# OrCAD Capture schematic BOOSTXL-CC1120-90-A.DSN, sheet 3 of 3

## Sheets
3 CC112x: size B
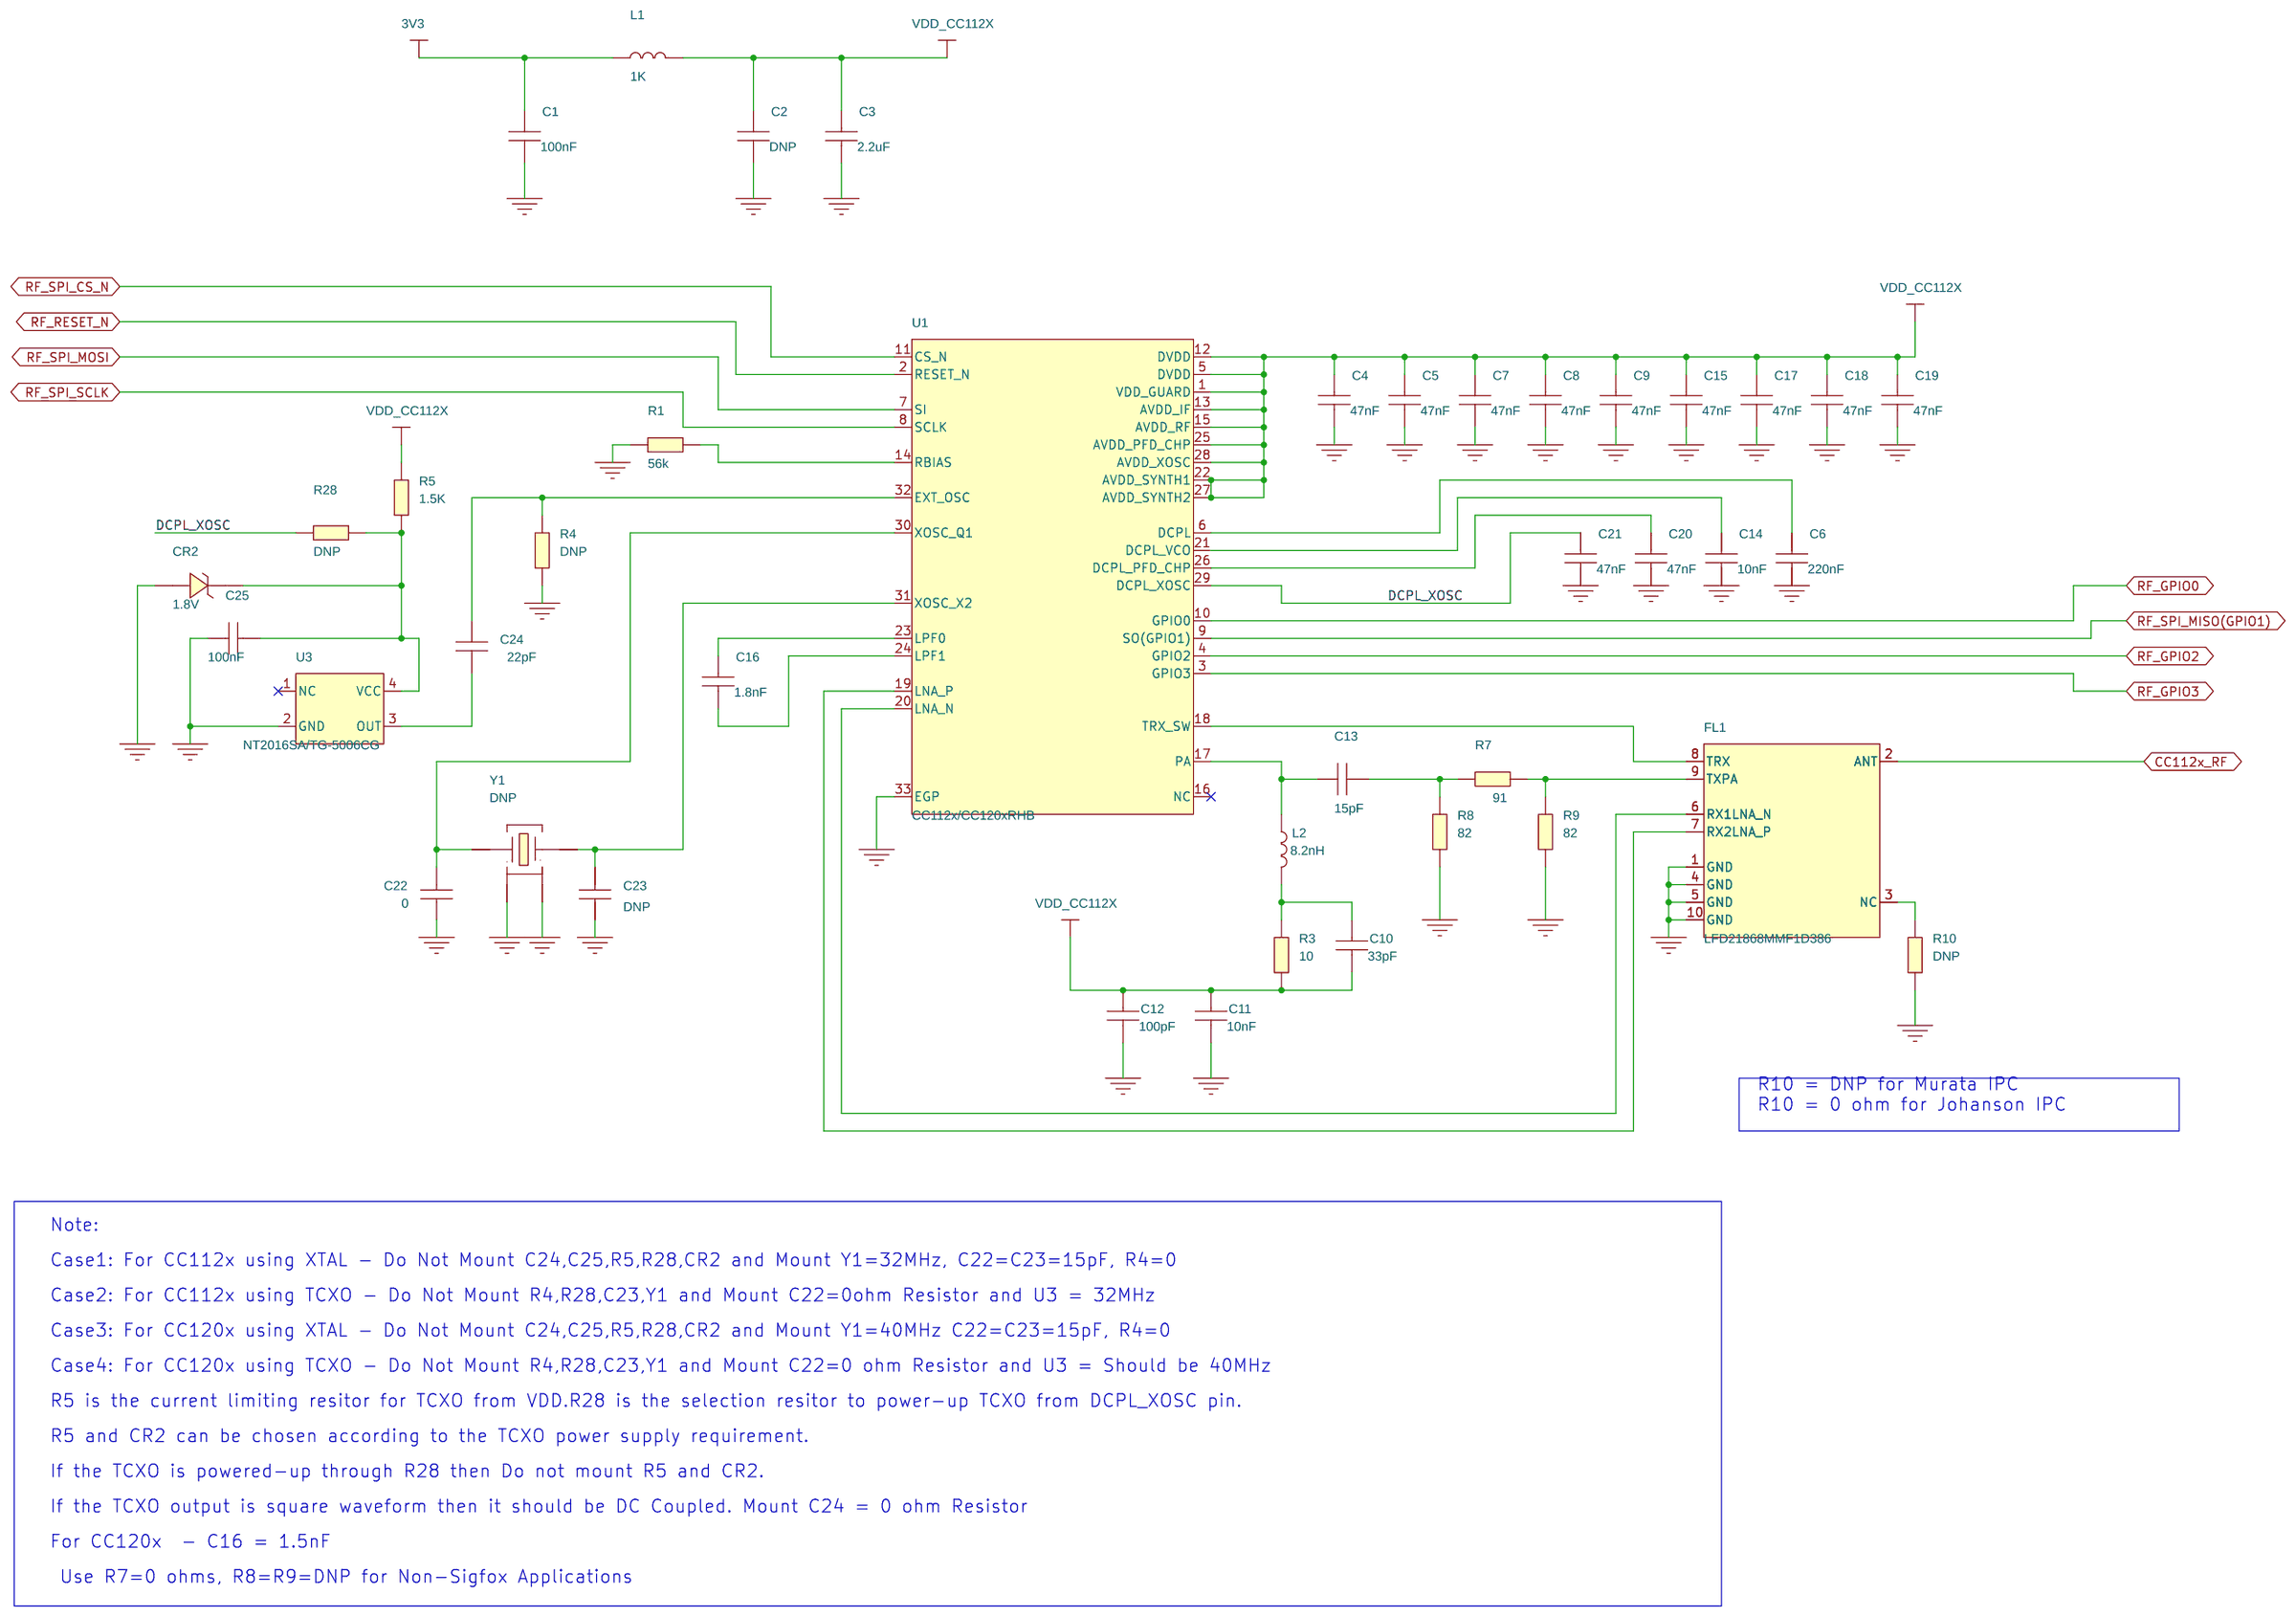
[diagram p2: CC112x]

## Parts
C1  100nF  [CAPC1005X60N]
C2  DNP  [CAPC1005X60N]
C3  2.2uF  [CAPC1608X90N]
C4  47nF  [CAPC1005X60N]
C5  47nF  [CAPC1005X60N]
C6  220nF  [CAPC1005X60N]
C7  47nF  [CAPC1005X60N]
C8  47nF  [CAPC1005X60N]
C9  47nF  [CAPC1005X60N]
C10  33pF  [CAPC1005X60N]
C11  10nF  [CAPC1005X60N]
C12  100pF  [CAPC1005X60N]
C13  15pF  [CAPC1005X60N]
C14  10nF  [CAPC1005X60N]
C15  47nF  [CAPC1005X60N]
C16  1.8nF  [CAPC1005X60N]
C17  47nF  [CAPC1005X60N]
C18  47nF  [CAPC1005X60N]
C19  47nF  [CAPC1005X60N]
C20  47nF  [CAPC1005X60N]
C21  47nF  [CAPC1005X60N]
C22  0  [CAPC1005X60N]
C23  DNP  [CAPC1005X60N]
C24  22pF  [CAPC1005X60N]
C25  100nF  [CAPC1005X60N]
CR2  1.8V  [SOD3716X135AN]
FL1  LFD21868MMF1D386  [FIL_LFD21868MMF1D386N]
L1  1K  [INDC1005X60N]
L2  8.2nH  [IND_LQW15AN]
R1  56k  [RESC1005X40N]
R3  10  [RESC1005X40N]
R4  DNP  [RESC1005X40N]
R5  1.5K  [RESC1005X40N]
R7  91  [RESC1005X40N]
R8  82  [RESC1005X40N]
R9  82  [RESC1005X40N]
R10  DNP  [RESC1005X40N]
R28  DNP  [RESC1005X40N]
U1  CC112x/CC120xRHB  [QFNFC50P500X500X100-33BN]
U3  NT2016SA/TG-5006CG  [OSCCC200X250X90-4BN]
Y1  DNP  [XTAL_FA128N]

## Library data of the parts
C1 C25 = CAPACITOR: CAPACITOR, CERAMIC X7R, 100nF, 10V, -10%/+10%, -55DEGC/+125DEGC, 0402, SMD; ALT_SYMBOLS: CAPC1005X60L,CAPC1005X60M; AutoDoc File: http://notefied-dynamic-precision.com/DB/Apps/Desktop/Item/Object.aspx?id=49911; Budget Currency: EUR; Budget Price: 0.006; Datasheet URL 1: http://search.murata.co.jp/Ceramy/image/img/w_hinm/L0005E.pdf; Datasheet URL 2: http://psearch.murata.com/capacitor/product/GRM155R71A104KA01%23.pdf; Definied Quality: INDUSTRIAL; Dielectric Type: X7R; Esd Level: N/A; FPLIST: CAPC1005X60N,CAPC1005X60L,CAPC1005X60M; Last Time Buy: N/A; Lead Time: 14; LifeCycle Status: GROWTH; MPN: GRM155R71A104KA01D; MPN Status: NRND; MSL: 1; MTBF: N/A; MTBF Standard: N/A; Manufacturer: MURATA; Max Oper Temp: +125DEGC; Max Tol: +10%; Min Oper Temp: -55DEGC; Min Tol: -10%; Mounting Type: SMD; NOTE Status: PREFERRED; Old Footprint: CAPC1005X60N,0402; PCB Package: 0402; Packing Size: 10000; Packing Type: TAPE_&_REEL; Part Number: 02-00760; Part Type: CAPACITOR\CERAMIC\0402; Revision: R008; RoHS Status: ROHS_COMPLIANT; Rtd Voltage: 10V; WEIGHT: 0.0016g
C2 = CAPACITOR: CAPACITOR, CERAMIC X7R, 100nF, 10V, -10%/+10%, -55DEGC/+125DEGC, 0402, SMD; ALT_SYMBOLS: CAPC1005X60L,CAPC1005X60M; AutoDoc File: http://notefied-dynamic-precision.com/DB/Apps/Desktop/Item/Object.aspx?id=49911; Budget Currency: EUR; Budget Price: 0.006; Capacitance: 100nF; Datasheet URL 1: http://search.murata.co.jp/Ceramy/image/img/w_hinm/L0005E.pdf; Datasheet URL 2: http://psearch.murata.com/capacitor/product/GRM155R71A104KA01%23.pdf; Definied Quality: INDUSTRIAL; Dielectric Type: X7R; Esd Level: N/A; FPLIST: CAPC1005X60N,CAPC1005X60L,CAPC1005X60M; Last Time Buy: N/A; Lead Time: 14; LifeCycle Status: GROWTH; MPN: GRM155R71A104KA01D; MPN Status: NRND; MSL: 1; MTBF: N/A; MTBF Standard: N/A; Manufacturer: MURATA; Max Oper Temp: +125DEGC; Max Tol: +10%; Min Oper Temp: -55DEGC; Min Tol: -10%; Mounting Type: SMD; NOTE Status: PREFERRED; Old Footprint: CAPC1005X60N,0402; PCB Package: 0402; Packing Size: 10000; Packing Type: TAPE_&_REEL; Part Number: 02-00760; Part Type: CAPACITOR\CERAMIC\0402; Revision: R008; RoHS Status: ROHS_COMPLIANT; Rtd Voltage: 10V; WEIGHT: 0.0016g
C3 = CAPACITOR: CAPACITOR, CERAMIC X5R, 2.2uF, 10V, -20%/+20%, -55DEGC/+85DEGC, 0603, SMD; ALT_SYMBOLS: CAPC1608X90L,CAPC1608X90M; AutoDoc File: http://notefied-dynamic-precision.com/DB/Apps/Desktop/Item/Object.aspx?id=50283; Budget Currency: EUR; Budget Price: 0.03; Datasheet URL 1: http://search.murata.co.jp/Ceramy/image/img/w_hinm/L0005E.pdf; Datasheet URL 2: http://psearch.murata.com/capacitor/product/GRM188R61A225ME34%23.pdf; Definied Quality: INDUSTRIAL; Dielectric Type: X5R; Esd Level: N/A; FPLIST: CAPC1608X90N,CAPC1608X90L,CAPC1608X90M; Last Time Buy: N/A; Lead Time: 10; LifeCycle Status: GROWTH; MPN: GRM188R61A225ME34D; MPN Status: NRND; MSL: 1; MTBF: N/A; MTBF Standard: N/A; Manufacturer: MURATA; Max Oper Temp: +85DEGC; Max Tol: +20%; Min Oper Temp: -55DEGC; Min Tol: -20%; Mounting Type: SMD; NOTE Status: PREFERRED; Old Footprint: CAPC1608X90N,0603; PCB Package: 0603; Packing Size: 4000; Packing Type: TAPE_&_REEL; Part Number: 02-01132; Part Type: CAPACITOR\CERAMIC\0603; Revision: R002; RoHS Status: ROHS_COMPLIANT; Rtd Voltage: 10V; WEIGHT: 0.0063g
C4 C5 C7-C9 C15 C17-C21 = CAPACITOR: CAPACITOR, CERAMIC, 47nF, 10%, X7R, 10V, 0402, SMD; ALT_SYMBOLS: CAPC1005X60L,CAPC1005X60M; AutoDoc File: http://notefied-dynamic-precision.com/DB/Apps/Desktop/Item/Object.aspx?id=49765; Budget Currency: EUR; Budget Price: 0.006; Datasheet URL 1: http://search.murata.co.jp/Ceramy/image/img/w_hinm/L0005E.pdf; Datasheet URL 2: http://psearch.murata.com/capacitor/product/GRM155R71A473KA01%23.pdf; Definied Quality: INDUSTRIAL; Dielectric Type: X7R; Esd Level: N/A; FPLIST: CAPC1005X60N,CAPC1005X60L,CAPC1005X60M; Last Time Buy: N/A; Lead Time: 10; LifeCycle Status: GROWTH; MPN: GRM155R71A473KA01D; MPN Status: NRND; MSL: 1; MTBF: N/A; MTBF Standard: N/A; Manufacturer: MURATA; Max Oper Temp: +125DEGC; Min Oper Temp: -55DEGC; Min Tol: -10%; Mounting Type: SMD; NOTE Status: PREFERRED; Old Footprint: CAPC1005X60N,0402; PCB Package: 0402; Packing Size: 10000; Packing Type: TAPE_&_REEL; Part Number: 02-00614; Part Type: CAPACITOR\CERAMIC\0402; Revision: R001; RoHS Status: ROHS_COMPLIANT; Rtd Voltage: 10V; WEIGHT: 0.0016g
C6 = CAPACITOR: CAPACITOR, CERAMIC X5R, 220nF, 10V, -10%/+10%, -55DEGC/+85DEGC, 0402, SMD; ALT_SYMBOLS: CAPC1005X60L,CAPC1005X60M; AutoDoc File: http://notefied-dynamic-precision.com/DB/Apps/Desktop/Item/Object.aspx?id=86035; Budget Currency: EUR; Budget Price: 0.014; Datasheet URL 1: http://search.murata.co.jp/Ceramy/image/img/w_hinm/L0005E.pdf; Datasheet URL 2: http://psearch.murata.com/capacitor/product/GRM155R61A224KE19%23.pdf; Definied Quality: INDUSTRIAL; Dielectric Type: X5R; Esd Level: N/A; FPLIST: CAPC1005X60N,CAPC1005X60L,CAPC1005X60M; Last Time Buy: N/A; Lead Time: 18; MPN: GRM155R61A224KE19D; MPN Status: ACTIVE; MSL: 1; MTBF: N/A; MTBF Standard: N/A; Manufacturer: MURATA; Max Oper Temp: +85DEGC; Max Tol: +10%; Min Oper Temp: -55DEGC; Min Tol: -10%; Mounting Type: SMD; NOTE Status: PREFERRED; PCB Package: 0402; Packing Size: 10000; Packing Type: TAPE_&_REEL; Part Number: 02-04353; Part Type: CAPACITOR\CERAMIC\0402; Revision: R001; RoHS Status: ROHS_COMPLIANT; Rtd Voltage: 10V; WEIGHT: 0.0016g
C10 = CAPACITOR: CAPACITOR, CERAMIC C0G/NP0, 33pF, 50V, -5%/+5%, -55DEGC/+125DEGC, 0402, SMD; ALT_SYMBOLS: CAPC1005X60M,CAPC1005X60L; AutoDoc File: http://notefied-dynamic-precision.com/DB/Apps/Desktop/Item/Object.aspx?id=86036; Budget Currency: EUR; Budget Price: 0.006; Datasheet URL 1: http://search.murata.co.jp/Ceramy/image/img/w_hinm/L0005E.pdf; Datasheet URL 2: http://psearch.murata.com/capacitor/product/GRM1555C1H330JA01%23.pdf; Definied Quality: INDUSTRIAL; Dielectric Type: C0G/NP0; Esd Level: N/A; FPLIST: CAPC1005X60N,CAPC1005X60M,CAPC1005X60L; Last Time Buy: N/A; Lead Time: 12; MPN: GRM1555C1H330JA01D; MPN Status: ACTIVE; MSL: 1; MTBF: N/A; MTBF Standard: N/A; Manufacturer: MURATA; Max Oper Temp: +125DEGC; Max TC: +30PPM/DEGC; Max Tol: +5%; Min Oper Temp: -55DEGC; Min TC: -30PPM/DEGC; Min Tol: -5%; Mounting Type: SMD; NOTE Status: PREFERRED; PCB Package: 0402; Packing Size: 10000; Packing Type: TAPE_&_REEL; Part Number: 02-04354; Part Type: CAPACITOR\CERAMIC\0402; Revision: R003; RoHS Status: ROHS_COMPLIANT; Rtd Voltage: 50V; WEIGHT: 0.0016g
C11 C14 = CAPACITOR: CAPACITOR, CERAMIC X7R, 10nF, 25V, -10%/+10%, -55DEGC/+125DEGC, 0402, SMD; ALT_SYMBOLS: CAPC1005X60L,CAPC1005X60M; AutoDoc File: http://notefied-dynamic-precision.com/DB/Apps/Desktop/Item/Object.aspx?id=73597; Budget Currency: EUR; Budget Price: 0.003; Cage Code: C0151; Datasheet URL 1: http://search.murata.co.jp/Ceramy/image/img/w_hinm/L0005E.pdf; Datasheet URL 2: http://psearch.murata.com/capacitor/product/GRM155R71E103KA01%23.pdf; Definied Quality: INDUSTRIAL; Dielectric Type: X7R; Esd Level: N/A; FPLIST: CAPC1005X60N,CAPC1005X60L,CAPC1005X60M; Last Time Buy: N/A; Lead Time: 10; MPN: GRM155R71E103KA01D; MPN Status: ACTIVE; MSL: N/A; MTBF: N/A; MTBF Standard: N/A; Manufacturer: MURATA; Max Oper Temp: +125DEGC; Max Tol: +10%; Min Oper Temp: -55DEGC; Min Tol: -10%; Mounting Type: SMD; NOTE Status: PREFERRED; PCB Package: 0402; Packing Size: 10000; Packing Type: TAPE_&_REEL; Part Number: 02-02314; Part Type: CAPACITOR\CERAMIC\0402; Revision: R002; RoHS Status: ROHS_COMPLIANT; Rtd Voltage: 25V; WEIGHT: 0.0016g
C12 = CAPACITOR: CAPACITOR, CERAMIC C0G/NP0, 100pF, 50V, -5%/+5%, -55DEGC/+125DEGC, 0402, SMD; ALT_SYMBOLS: CAPC1005X60L,CAPC1005X60M; AutoDoc File: http://notefied-dynamic-precision.com/DB/Apps/Desktop/Item/Object.aspx?id=86072; Budget Currency: EUR; Budget Price: 0.006; Datasheet URL 1: http://search.murata.co.jp/Ceramy/image/img/w_hinm/L0005E.pdf; Datasheet URL 2: http://psearch.murata.com/capacitor/product/GRM1555C1H101JA01%23.pdf; Definied Quality: INDUSTRIAL; Dielectric Type: C0G/NP0; Esd Level: N/A; FPLIST: CAPC1005X60N,CAPC1005X60L,CAPC1005X60M; Last Time Buy: N/A; Lead Time: 12; MPN: GRM1555C1H101JA01D; MPN Status: ACTIVE; MSL: 1; MTBF: N/A; MTBF Standard: N/A; Manufacturer: MURATA; Max Oper Temp: +125DEGC; Max TC: +30PPM/DEGC; Max Tol: +5%; Min Oper Temp: -55DEGC; Min TC: -30PPM/DEGC; Min Tol: -5%; Mounting Type: SMD; NOTE Status: PREFERRED; PCB Package: 0402; Packing Size: 10000; Packing Type: TAPE_&_REEL; Part Number: 02-04365; Part Type: CAPACITOR\CERAMIC\0402; Revision: R002; RoHS Status: ROHS_COMPLIANT; Rtd Voltage: 50V; WEIGHT: 0.0016g
C13 = CAPACITOR: CAPACITOR, CERAMIC C0G/NP0, 15pF, 50V, -5%/+5%, -55DEGC/+125DEGC, 0402, SMD; ALT_SYMBOLS: CAPC1005X60L,CAPC1005X60M; AutoDoc File: http://notefied-dynamic-precision.com/DB/Apps/Desktop/Item/Object.aspx?id=87791; Budget Currency: EUR; Budget Price: 0.005; Datasheet URL 1: http://search.murata.co.jp/Ceramy/image/img/w_hinm/L0005E.pdf; Datasheet URL 2: http://psearch.murata.com/capacitor/product/GRM1555C1H150JA01%23.pdf; Definied Quality: INDUSTRIAL; Dielectric Type: C0G/NP0; Esd Level: N/A; FPLIST: CAPC1005X60N,CAPC1005X60L,CAPC1005X60M; Last Time Buy: N/A; Lead Time: 12; MPN: GRM1555C1H150JA01D; MPN Status: ACTIVE; MSL: 1; MTBF: N/A; MTBF Standard: N/A; Manufacturer: MURATA; Max Oper Temp: +125DEGC; Max TC: +30PPM/DEGC; Max Tol: +5%; Min Oper Temp: -55DEGC; Min TC: -30PPM/DEGC; Min Tol: -5%; Mounting Type: SMD; NOTE Status: PREFERRED; PCB Package: 0402; Packing Size: 10000; Packing Type: TAPE_&_REEL; Part Number: 02-04673; Part Type: CAPACITOR\CERAMIC\0402; Revision: R001; RoHS Status: ROHS_COMPLIANT; Rtd Voltage: 50V; WEIGHT: 0.0016g
C16 = CAPACITOR: CAPACITOR, CERAMIC U2J, 1.8nF, 10V, -5%/+5%, -55DEGC/+125DEGC, 0402, SMD; ALT_SYMBOLS: CAPC1005X60L,CAPC1005X60M; AutoDoc File: http://notefied-dynamic-precision.com/DB/Apps/Desktop/Item/Object.aspx?id=86079; Budget Currency: EUR; Budget Price: 0.028; Datasheet URL 1: http://search.murata.co.jp/Ceramy/image/img/w_hinm/L0005E.pdf; Datasheet URL 2: http://psearch.murata.com/capacitor/product/GRM1557U1A182JA01%23.pdf; Definied Quality: INDUSTRIAL; Dielectric Type: U2J; Esd Level: N/A; FPLIST: CAPC1005X60N,CAPC1005X60L,CAPC1005X60M; Last Time Buy: N/A; Lead Time: 12; MPN: GRM1557U1A182JA01D; MPN Status: ACTIVE; MSL: 1; MTBF: N/A; MTBF Standard: N/A; Manufacturer: MURATA; Max Oper Temp: +125DEGC; Max TC: +120PPM/DEGC; Max Tol: +5%; Min Oper Temp: -55DEGC; Min TC: -750PPM/DEGC; Min Tol: -5%; Mounting Type: SMD; NOTE Status: PREFERRED; PCB Package: 0402; Packing Size: 10000; Packing Type: TAPE_&_REEL; Part Number: 02-04371; Part Type: CAPACITOR\CERAMIC\0402; Revision: R001; RoHS Status: ROHS_COMPLIANT; Rtd Voltage: 10V; WEIGHT: 0.0016g
C22 C23 = CAPACITOR: CAPACITOR, CERAMIC C0G/NP0, 15pF, 50V, -5%/+5%, -55DEGC/+125DEGC, 0402, SMD; ALT_SYMBOLS: CAPC1005X60L,CAPC1005X60M; AutoDoc File: http://notefied-dynamic-precision.com/DB/Apps/Desktop/Item/Object.aspx?id=87791; Budget Currency: EUR; Budget Price: 0.005; Capacitance: 15pF; Datasheet URL 1: http://search.murata.co.jp/Ceramy/image/img/w_hinm/L0005E.pdf; Datasheet URL 2: http://psearch.murata.com/capacitor/product/GRM1555C1H150JA01%23.pdf; Definied Quality: INDUSTRIAL; Dielectric Type: C0G/NP0; Esd Level: N/A; FPLIST: CAPC1005X60N,CAPC1005X60L,CAPC1005X60M; Last Time Buy: N/A; Lead Time: 12; MPN: GRM1555C1H150JA01D; MPN Status: ACTIVE; MSL: 1; MTBF: N/A; MTBF Standard: N/A; Manufacturer: MURATA; Max Oper Temp: +125DEGC; Max TC: +30PPM/DEGC; Max Tol: +5%; Min Oper Temp: -55DEGC; Min TC: -30PPM/DEGC; Min Tol: -5%; Mounting Type: SMD; NOTE Status: PREFERRED; PCB Package: 0402; Packing Size: 10000; Packing Type: TAPE_&_REEL; Part Number: 02-04673; Part Type: CAPACITOR\CERAMIC\0402; Revision: R001; RoHS Status: ROHS_COMPLIANT; Rtd Voltage: 50V; WEIGHT: 0.0016g
C24 = CAPACITOR: CAPACITOR, CERAMIC C0G/NP0, 22pF, 50V, -5%/+5%, -55DEGC/+125DEGC, 0402, SMD; ALT_SYMBOLS: CAPC1005X60L,CAPC1005X60M; AutoDoc File: http://notefied-dynamic-precision.com/DB/Apps/Desktop/Item/Object.aspx?id=86084; Budget Currency: EUR; Budget Price: 0.005; Datasheet URL 1: http://search.murata.co.jp/Ceramy/image/img/w_hinm/L0005E.pdf; Datasheet URL 2: http://psearch.murata.com/capacitor/product/GRM1555C1H220JA01%23.pdf; Definied Quality: INDUSTRIAL; Dielectric Type: C0G/NP0; Esd Level: N/A; FPLIST: CAPC1005X60N,CAPC1005X60L,CAPC1005X60M; Last Time Buy: N/A; Lead Time: 12; MPN: GRM1555C1H220JA01D; MPN Status: ACTIVE; MSL: 1; MTBF: N/A; MTBF Standard: N/A; Manufacturer: MURATA; Max Oper Temp: +125DEGC; Max Tol: +5%; Min Oper Temp: -55DEGC; Min Tol: -5%; Mounting Type: SMD; NOTE Status: PREFERRED; PCB Package: 0402; Packing Size: 10000; Packing Type: TAPE_&_REEL; Part Number: 02-04373; Part Type: CAPACITOR\CERAMIC\0402; Revision: R003; RoHS Status: ROHS_COMPLIANT; Rtd Voltage: 50V; WEIGHT: 0.0016g
CR2 = DIODE_ZENER_0: DIODE, ZENER, 1.8V@50uA, 0.01A, 0.5W, -55DEGC/+150DEGC, SOD-123, SMD; ALT_SYMBOLS: SOD3716X135AL,SOD3716X135AM; AutoDoc File: http://notefied-dynamic-precision.com/DB/Apps/Desktop/Item/Object.aspx?id=56117; Budget Currency: USD; Budget Price: 0.042; Datasheet URL 1: http://www.onsemi.com/pub/Collateral/425-04.PDF; Datasheet URL 2: http://www.onsemi.com/pub/Collateral/MMSZ4678T1-D.PDF; Definied Quality: INDUSTRIAL; Esd Level: HBM 16kV; FPLIST: SOD3716X135AN,SOD3716X135AL,SOD3716X135AM; Last Time Buy: N/A; Lead Time: 24; LifeCycle Status: ACTIVE; MPN: MMSZ4678T1G; MPN Status: ACTIVE; MSL: 1; MTBF: 8.71*10^9; MTBF Standard: CL=90%,Tj=25degC,Ea=0.7eV; Manufacturer: ON SEMICONDUCTOR; Max Oper Temp: +150DEGC; Min Oper Temp: -55DEGC; Mounting Type: SMD; NOTE Status: PREFERRED; PCB Package: SOD-123; Packing Size: 3000; Packing Type: TAPE_&_REEL; Part Number: 14-04601; Part Type: DIODE\ZENER; Revision: R002; RoHS Status: ROHS_COMPLIANT; Rtd Current: 0.01A; Rtd Power: 0.5W; WEIGHT: 0.01167g
FL1 = FILTER_LFD21868MMF1D386: FILTER, OTHER, 50@891.5MHz, -40DEGC/+85DEGC, SMD; ALT_SYMBOLS: FIL_LFD21868MMF1D386L,FIL_LFD21868MMF1D386M; AutoDoc File: http://notefied-dynamic-precision.com/DB/Apps/Desktop/Item/Object.aspx?id=89127; Budget Currency: EUR; Budget Price: 0.149; Datasheet URL 1: http://search.murata.co.jp/Ceramy/image/img/w_hinm/S0296E.pdf; Datasheet URL 2: http://search.murata.co.jp/Ceramy/image/img/A05X/D386.pdf; Definied Quality: INDUSTRIAL; Esd Level: N/A; FPLIST: FIL_LFD21868MMF1D386N,FIL_LFD21868MMF1D386L,FIL_LFD21868MMF1D386M; Frequency: 891.5MHz; Impedance: 50; Last Time Buy: N/A; Lead Time: 12; MPN Status: ACTIVE; MSL: N/A; MTBF: N/A; MTBF Standard: N/A; Manufacturer: MURATA; Max Oper Temp: +85DEGC; Min Oper Temp: -40DEGC; Mounting Type: SMD; NOTE Status: PREFERRED; Packing Size: 4000; Packing Type: TAPE_&_REEL; Part Number: 04-00527; Part Type: FILTER\OTHER; Revision: R002; RoHS Status: ROHS_COMPLIANT; Rtd Power: 0.5W; WEIGHT: N/A
L1 = INDUCTOR_2: FILTER, EMI, 1000@100MHz, -55DEGC/+125DEGC, 0402, SMD; ALT_SYMBOLS: INDC1005X60L,INDC1005X60M; AutoDoc File: http://notefied-dynamic-precision.com/DB/Apps/Desktop/Item/Object.aspx?id=15260; Budget Currency: EUR; Budget Price: 0.05; Datasheet URL 1: http://search.murata.co.jp/Ceramy/image/img/w_hinm/L0110E.pdf; Datasheet URL 2: http://search.murata.co.jp/Ceramy/image/img/PDF/ENG/L0110S0101BLM15H.pdf; Definied Quality: INDUSTRIAL; Esd Level: N/A; FPLIST: INDC1005X60N,INDC1005X60L,INDC1005X60M; Frequency: 100MHz; Impedance: 1000@100MHz; Last Time Buy: N/A; Lead Time: 8; LifeCycle Status: ACTIVE; MPN: BLM15HG102SN1D; MPN Status: ACTIVE; MSL: N/A; MTBF: N/A; MTBF Standard: N/A; Manufacturer: MURATA; Max Oper Temp: +125DEGC; Max Tol: +25%; Min Oper Temp: -55DEGC; Min Tol: -25%; Mounting Type: SMD; NOTE Status: PREFERRED; Old Footprint: INDC1005X60N,0402; PCB Package: 0402; Packing Size: 10000; Packing Type: TAPE_&_REEL; Part Number: 04-00032; Part Type: FILTER\EMI\0402; Resistance: 1.1; Revision: R002; RoHS Status: ROHS_COMPLIANT; Rtd Current: 0.25A; WEIGHT: 0.001g
L2 = INDUCTOR_3: INDUCTOR, CHIP, 8.2nH, -2%/+2%, 0.54A, -55DEGC/+125DEGC, 0402, SMD; ALT_SYMBOLS: IND_LQW15AM,IND_LQW15AL; AutoDoc File: http://notefied-dynamic-precision.com/DB/Apps/Desktop/Item/Object.aspx?id=86089; Budget Currency: EUR; Budget Price: 0.128; Datasheet URL 1: N/A; Datasheet URL 2: http://psearch.murata.com/inductor/product/LQW15AN8N2G00%23.pdf; Definied Quality: INDUSTRIAL; Esd Level: N/A; FPLIST: IND_LQW15AN,IND_LQW15AM,IND_LQW15AL; Frequency: 5.5GHz; Last Time Buy: N/A; Lead Time: 9; MPN: LQW15AN8N2G00D; MPN Status: NRND; MSL: N/A; MTBF: N/A; MTBF Standard: N/A; Manufacturer: MURATA; Max Oper Temp: +125DEGC; Max Tol: +2%; Min Oper Temp: -55DEGC; Min Tol: -2%; Mounting Type: SMD; NOTE Status: PREFERRED; PCB Package: 0402; Packing Size: 10000; Packing Type: TAPE_&_REEL; Part Number: 03-06557; Part Type: INDUCTOR\CHIP\0402; Resistance: 0.14; Revision: R001; RoHS Status: ROHS_COMPLIANT; Rtd Current: 0.54A; WEIGHT: 0.0008g
R1 = RESISTOR: RESISTOR, THICK FILM, 56k, -5%/+5%, 0.063W, 50V, -55DEGC/+155DEGC, 0402, SMD; ALT_SYMBOLS: RESC1005X40L,RESC1005X40M; AutoDoc File: http://notefied-dynamic-precision.com/DB/Apps/Desktop/Item/Object.aspx?id=75757; Budget Currency: USD; Budget Price: 0.00244; Datasheet URL 1: N/A; Datasheet URL 2: N/A; Definied Quality: INDUSTRIAL; Esd Level: N/A; FPLIST: RESC1005X40N,RESC1005X40L,RESC1005X40M; Last Time Buy: N/A; Lead Time: N/A; LifeCycle Status: ACTIVE; MPN: RESISTOR_0402_56k_+/-5%_50V_0.063W_M_+/-200ppm; MPN Status: ACTIVE; MSL: N/A; MTBF: N/A; MTBF Standard: N/A; Manufacturer: MANUFACTURER SELECTION; Max Oper Temp: +155DEGC; Max TC: +200PPM/DEGC; Max Tol: +5%; Min Oper Temp: -55DEGC; Min TC: -200PPM/DEGC; Min Tol: -5%; Mounting Type: SMD; NOTE Status: PREFERRED; PCB Package: 0402; Packing Size: 10000; Packing Type: TAPE_&_REEL; Part Number: 01-11702; Part Type: RESISTOR\0402; Resistor Type: THICK FILM; Revision: R000; RoHS Status: ROHS_COMPLIANT; Rtd Power: 0.063W; Rtd Voltage: 50V; WEIGHT: N/A
R3 = RESISTOR: RESISTOR, THICK FILM, 10, -5%/+5%, 0.063W, 50V, -55DEGC/+155DEGC, 0402, SMD; ALT_SYMBOLS: RESC1005X40L,RESC1005X40M; AutoDoc File: http://notefied-dynamic-precision.com/DB/Apps/Desktop/Item/Object.aspx?id=75667; Budget Currency: USD; Budget Price: 0.00244; Datasheet URL 1: N/A; Datasheet URL 2: N/A; Definied Quality: INDUSTRIAL; Esd Level: N/A; FPLIST: RESC1005X40N,RESC1005X40L,RESC1005X40M; Last Time Buy: N/A; Lead Time: N/A; LifeCycle Status: ACTIVE; MPN: RESISTOR_0402_10_+/-5%_50V_0.063W_M_+/-200ppm; MPN Status: ACTIVE; MSL: N/A; MTBF: N/A; MTBF Standard: N/A; Manufacturer: MANUFACTURER SELECTION; Max Oper Temp: +155DEGC; Max TC: +200PPM/DEGC; Max Tol: +5%; Min Oper Temp: -55DEGC; Min TC: -200PPM/DEGC; Min Tol: -5%; Mounting Type: SMD; NOTE Status: PREFERRED; PCB Package: 0402; Packing Size: 10000; Packing Type: TAPE_&_REEL; Part Number: 01-11612; Part Type: RESISTOR\0402; Resistor Type: THICK FILM; Revision: R000; RoHS Status: ROHS_COMPLIANT; Rtd Power: 0.063W; Rtd Voltage: 50V; WEIGHT: N/A
R4 R10 R28 = RESISTOR: RESISTOR, THICK FILM, 0, -5%/+5%, 0.063W, 50V, -55DEGC/+155DEGC, 0402, SMD; ALT_SYMBOLS: RESC1005X40L,RESC1005X40M; AutoDoc File: http://notefied-dynamic-precision.com/DB/Apps/Desktop/Item/Object.aspx?id=75642; Budget Currency: USD; Budget Price: 0.00244; Datasheet URL 1: N/A; Datasheet URL 2: N/A; Definied Quality: INDUSTRIAL; Esd Level: N/A; FPLIST: RESC1005X40N,RESC1005X40L,RESC1005X40M; Last Time Buy: N/A; Lead Time: N/A; LifeCycle Status: ACTIVE; MPN: RESISTOR_0402_0_+/-5%_50V_0.063W_M_+/-200ppm; MPN Status: ACTIVE; MSL: N/A; MTBF: N/A; MTBF Standard: N/A; Manufacturer: MANUFACTURER SELECTION; Max Oper Temp: +155DEGC; Max TC: +200PPM/DEGC; Max Tol: +5%; Min Oper Temp: -55DEGC; Min TC: -200PPM/DEGC; Min Tol: -5%; Mounting Type: SMD; NOTE Status: PREFERRED; PCB Package: 0402; Packing Size: 10000; Packing Type: TAPE_&_REEL; Part Number: 01-11587; Part Type: RESISTOR\0402; Resistance: 0; Resistor Type: THICK FILM; Revision: R001; RoHS Status: ROHS_COMPLIANT; Rtd Power: 0.063W; Rtd Voltage: 50V; WEIGHT: N/A
R5 = RESISTOR: RESISTOR, THICK FILM, 470, -5%/+5%, 0.063W, 50V, -55DEGC/+155DEGC, 0402, SMD; ALT_SYMBOLS: RESC1005X40L,RESC1005X40M; AutoDoc File: http://notefied-dynamic-precision.com/DB/Apps/Desktop/Item/Object.aspx?id=75707; Budget Currency: USD; Budget Price: 0.00244; Datasheet URL 1: N/A; Datasheet URL 2: N/A; Definied Quality: INDUSTRIAL; Esd Level: N/A; FPLIST: RESC1005X40N,RESC1005X40L,RESC1005X40M; Last Time Buy: N/A; Lead Time: N/A; LifeCycle Status: ACTIVE; MPN: RESISTOR_0402_470_+/-5%_50V_0.063W_M_+/-200ppm; MPN Status: ACTIVE; MSL: N/A; MTBF: N/A; MTBF Standard: N/A; Manufacturer: MANUFACTURER SELECTION; Max Oper Temp: +155DEGC; Max TC: +200PPM/DEGC; Max Tol: +5%; Min Oper Temp: -55DEGC; Min TC: -200PPM/DEGC; Min Tol: -5%; Mounting Type: SMD; NOTE Status: PREFERRED; PCB Package: 0402; Packing Size: 10000; Packing Type: TAPE_&_REEL; Part Number: 01-11652; Part Type: RESISTOR\0402; Resistance: 470; Resistor Type: THICK FILM; Revision: R000; RoHS Status: ROHS_COMPLIANT; Rtd Power: 0.063W; Rtd Voltage: 50V; WEIGHT: N/A
R7 = RESISTOR: RESISTOR, THICK FILM, 91, -5%/+5%, 0.063W, 50V, -55DEGC/+155DEGC, 0402, SMD; ALT_SYMBOLS: RESC1005X40L,RESC1005X40M; AutoDoc File: http://notefied-dynamic-precision.com/DB/Apps/Desktop/Item/Object.aspx?id=75690; Budget Currency: USD; Budget Price: 0.00244; Datasheet URL 1: N/A; Datasheet URL 2: N/A; Definied Quality: INDUSTRIAL; Esd Level: N/A; FPLIST: RESC1005X40N,RESC1005X40L,RESC1005X40M; Last Time Buy: N/A; Lead Time: N/A; LifeCycle Status: ACTIVE; MPN: RESISTOR_0402_91_+/-5%_50V_0.063W_M_+/-200ppm; MPN Status: ACTIVE; MSL: N/A; MTBF: N/A; MTBF Standard: N/A; Manufacturer: MANUFACTURER SELECTION; Max Oper Temp: +155DEGC; Max TC: +200PPM/DEGC; Max Tol: +5%; Min Oper Temp: -55DEGC; Min TC: -200PPM/DEGC; Min Tol: -5%; Mounting Type: SMD; NOTE Status: PREFERRED; PCB Package: 0402; Packing Size: 10000; Packing Type: TAPE_&_REEL; Part Number: 01-11635; Part Type: RESISTOR\0402; Resistor Type: THICK FILM; Revision: R000; RoHS Status: ROHS_COMPLIANT; Rtd Power: 0.063W; Rtd Voltage: 50V; WEIGHT: N/A
R8 R9 = RESISTOR: RESISTOR, THICK FILM, 82, -5%/+5%, 0.063W, 50V, -55DEGC/+155DEGC, 0402, SMD; ALT_SYMBOLS: RESC1005X40L,RESC1005X40M; AutoDoc File: http://notefied-dynamic-precision.com/DB/Apps/Desktop/Item/Object.aspx?id=75689; Budget Currency: USD; Budget Price: 0.00244; Datasheet URL 1: N/A; Datasheet URL 2: N/A; Definied Quality: INDUSTRIAL; Esd Level: N/A; FPLIST: RESC1005X40N,RESC1005X40L,RESC1005X40M; Last Time Buy: N/A; Lead Time: N/A; LifeCycle Status: ACTIVE; MPN: RESISTOR_0402_82_+/-5%_50V_0.063W_M_+/-200ppm; MPN Status: ACTIVE; MSL: N/A; MTBF: N/A; MTBF Standard: N/A; Manufacturer: MANUFACTURER SELECTION; Max Oper Temp: +155DEGC; Max TC: +200PPM/DEGC; Max Tol: +5%; Min Oper Temp: -55DEGC; Min TC: -200PPM/DEGC; Min Tol: -5%; Mounting Type: SMD; NOTE Status: PREFERRED; PCB Package: 0402; Packing Size: 10000; Packing Type: TAPE_&_REEL; Part Number: 01-11634; Part Type: RESISTOR\0402; Resistor Type: THICK FILM; Revision: R000; RoHS Status: ROHS_COMPLIANT; Rtd Power: 0.063W; Rtd Voltage: 50V; WEIGHT: N/A
U1 = IC_RF_CC1120_QFN32: IC, ANALOG RF, CC120xRHB, N/A, QFN32, SMD; ALT_SYMBOLS: QFNFC50P500X500X100-33BL,QFNFC50P500X500X100-33BM; AutoDoc File: http://notefied-dynamic-precision.com/DB/Apps/Desktop/Item/Object.aspx?id=87160; Budget Currency: N/A; Budget Price: N/A; Datasheet URL 1: N/A; Datasheet URL 2: www.ti.com; Definied Quality: COMMERCIAL; Esd Level: N/A; FPLIST: QFNFC50P500X500X100-33BN,QFNFC50P500X500X100-33BL,QFNFC50P500X500X100-33BM; Last Time Buy: N/A; Lead Time: N/A; MPN: CC120XRHB; MPN Status: ACTIVE; MSL: N/A; MTBF: N/A; MTBF Standard: N/A; Manufacturer: TEXAS INSTRUMENTS; Max Oper Temp: N/A; Min Oper Temp: N/A; Mounting Type: SMD; NOTE Status: PREFERRED; PCB Package: QFN32; Packing Size: 2500; Packing Type: TAPE_&_REEL; Part Number: 18-28112; Part Type: IC\ANALOG\RF\TRANSCEIVER; Revision: R001; RoHS Status: ROHS_COMPLIANT; Rtd Voltage: N/A; WEIGHT: N/A
U3 = XTAL_TG-5021CG: CRYSTAL, OSCILATOR, TBD, 2.3V TO 3.6V, -30DEGC/+85DEGC, SMD; ALT_SYMBOLS: OSCCC200X250X90-4BL,OSCCC200X250X90-4BM; AutoDoc File: http://notefied-dynamic-precision.com/DB/Apps/Desktop/Item/Object.aspx?id=86099; Budget Currency: N/A; Budget Price: N/A; Capacitance: 10pF; Datasheet URL 1: N/A; Datasheet URL 2: http://www.eea.epson.com/portal/pls/portal/docs/1/1547465.PDF; Definied Quality: COMMERCIAL; Esd Level: N/A; FPLIST: OSCCC200X250X90-4BN,OSCCC200X250X90-4BL,OSCCC200X250X90-4BM; Frequency: TBD; Last Time Buy: N/A; Lead Time: N/A; MPN: TG_5021CG; MPN Status: ACTIVE; MSL: N/A; MTBF: N/A; MTBF Standard: N/A; Manufacturer: EPSON; Max Oper Temp: +85DEGC; Min Oper Temp: -30DEGC; Mounting Type: SMD; NOTE Status: PREFERRED; Packing Size: N/A; Packing Type: N/A; Part Number: 12-00451; Part Type: CRYSTAL\OSCILLATOR; Revision: R001; RoHS Status: ROHS_COMPLIANT; Rtd Voltage: 2.3V TO 3.6V; WEIGHT: N/A
Y1 = XTAL_4: CRYSTAL, OSCILATOR, 32MHz, 10pF, -10PPM/+10PPM, -40DEGC/+85DEGC, SMD; ALT_SYMBOLS: XTAL_FA128L,XTAL_FA128M; AutoDoc File: http://notefied-dynamic-precision.com/DB/Apps/Desktop/Item/Object.aspx?id=85460; Budget Currency: EUR; Budget Price: 0.545; Capacitance: 10pF; Datasheet URL 1: http://www.eea.epson.com/portal/pls/portal/docs/1/1529523.PDF; Datasheet URL 2: http://www.eea.epson.com/portal/pls/portal/docs/1/1529449.PDF; Definied Quality: INDUSTRIAL; Esd Level: N/A; FPLIST: XTAL_FA128N,XTAL_FA128L,XTAL_FA128M; Frequency: 32MHz; Last Time Buy: N/A; Lead Time: 13; MPN: FA-128 32MHz 10pF 10ppm; MPN Status: ACTIVE; MSL: N/A; MTBF: N/A; MTBF Standard: N/A; Manufacturer: EPSON; Max Oper Temp: +85DEGC; Max Tol: +10PPM; Min Oper Temp: -40DEGC; Min Tol: -10PPM; Mounting Type: SMD; NOTE Status: PREFERRED; PCB Package: SMD; Packing Size: 250; Packing Type: TAPE_&_REEL; Part Number: 12-00422; Part Type: CRYSTAL\OSCILLATOR\MEMS; Revision: R001; RoHS Status: ROHS_COMPLIANT; WEIGHT: N/A

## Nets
3V3: C1.1 L1.1 ; also on sheet 1 2
GND: C1.2 C2.2 C3.2 C4.2 C5.2 C6.2 C7.2 C8.2 C9.2 C11.2 C12.2 C14.2 C15.2 C17.2 C18.2 C19.2 C20.2 C21.2 C22.1 C23.1 C25.1 CR2.2(ANODE) FL1.1(GND) FL1.4(GND) FL1.5(GND) FL1.10(GND) R1.2 R4.1 R8.1 R9.1 R10.1 U1.33(EGP) U3.2(GND) Y1.2 Y1.4 ; also on sheet 1 2
VDD_CC112x: C2.1 C3.1 C4.1 C5.1 C7.1 C8.1 C9.1 C10.2 C11.1 C12.1 C15.1 C17.1 C18.1 C19.1 L1.2 R3.1 R5.2 U1.1(VDD_GUARD) U1.5(DVDD) U1.12(DVDD) U1.13(AVDD_IF) U1.15(AVDD_RF) U1.22(AVDD_SYNTH1) U1.25(AVDD_PFD_CHP) U1.27(AVDD_SYNTH2) U1.28(AVDD_XOSC)
CC112x_RF: FL1.2(ANT) ; also on sheet 2
DCPL_XOSC: C21.1 R28.2 U1.29(DCPL_XOSC)
RF_GPIO0: U1.10(GPIO0) ; also on sheet 1 2
RF_GPIO2: U1.4(GPIO2) ; also on sheet 1 2
RF_GPIO3: U1.3(GPIO3) ; also on sheet 1
RF_RESET_N: U1.2(RESET_N) ; also on sheet 1
RF_SPI_CS_N: U1.11(CS_N) ; also on sheet 1
RF_SPI_MISO(GPIO1): U1.9(SO(GPIO1)) ; also on sheet 1
RF_SPI_MOSI: U1.7(SI) ; also on sheet 1
RF_SPI_SCLK: U1.8(SCLK) ; also on sheet 1
N333157: C13.1 L2.1 U1.17(PA)
N333170: C10.1 L2.2 R3.2
N333547: C13.2 R7.2 R8.2
N333561: FL1.9(TXPA) R7.1 R9.2
N333614: FL1.8(TRX) U1.18(TRX_SW)
N333626: FL1.6(RX1LNA_N) U1.20(LNA_N)
N333651: FL1.7(RX2LNA_P) U1.19(LNA_P)
N334768: R1.1 U1.14(RBIAS)
N334780: C16.2 U1.24(LPF1)
N334837: C16.1 U1.23(LPF0)
N335035: C25.2 CR2.1(CATHODE) R5.1 R28.1 U3.4(VCC)
N335193: C22.2 U1.30(XOSC_Q1) Y1.1
N335253: C23.2 U1.31(XOSC_X2) Y1.3
N337409: FL1.3(NC) R10.2
N339345: C20.1 U1.26(DCPL_PFD_CHP)
N339363: C14.1 U1.21(DCPL_VCO)
N339381: C6.1 U1.6(DCPL)
N340434: C24.1 R4.2 U1.32(EXT_OSC)
N340490: C24.2 U3.3(OUT)

Not connected (* = marked no-connect by the designer): U1 16(NC)*; U3 1(NC)*

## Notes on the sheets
sheet 3
- R10 = DNP for Murata IPC
  R10 = 0 ohm for Johanson IPC
- Note:
- Case1: For CC112x using XTAL - Do Not Mount C24,C25,R5,R28,CR2 and Mount Y1=32MHz, C22=C23=15pF, R4=0
- Case2: For CC112x using TCXO - Do Not Mount R4,R28,C23,Y1 and Mount C22=0ohm Resistor and U3 = 32MHz
- Case3: For CC120x using XTAL - Do Not Mount C24,C25,R5,R28,CR2 and Mount Y1=40MHz C22=C23=15pF, R4=0
- Case4: For CC120x using TCXO - Do Not Mount R4,R28,C23,Y1 and Mount C22=0 ohm Resistor and U3 = Should be 40MHz
- R5 is the current limiting resitor for TCXO from VDD.R28 is the selection resitor to power-up TCXO from DCPL_XOSC pin.
- R5 and CR2 can be chosen according to the TCXO power supply requirement.
- If the TCXO is powered-up through R28 then Do not mount R5 and CR2.
- If the TCXO output is square waveform then it should be DC Coupled. Mount C24 = 0 ohm Resistor
- For CC120x  - C16 = 1.5nF
- Use R7=0 ohms, R8=R9=DNP for Non-Sigfox Applications
